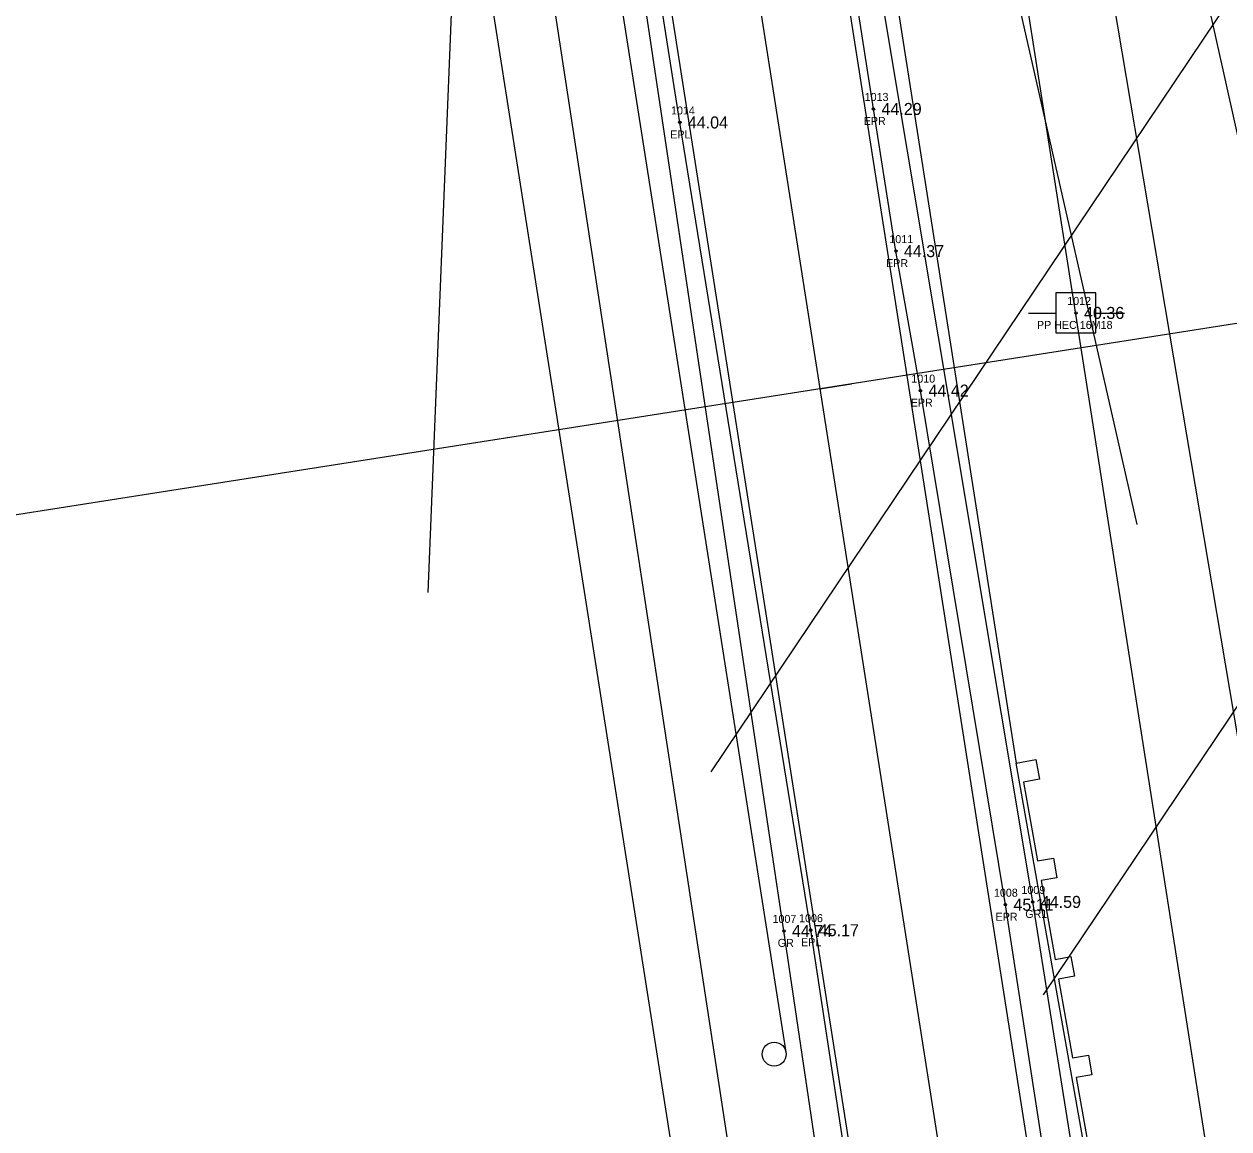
# Model space of a CAD drawing. Extents: x 2619568 to 2620316, y 784340 to 785138.
# Drawn here: x 2619755.9 to 2619906.4, y 784608.4 to 784746.5 of the extents above; entities that cross this region are included whole.
import ezdxf

# ---------------------------------------------------------------- set-up
doc = ezdxf.new("R2010")
doc.units = 0
for name, color, linetype in [('RD_EX_GuardRail', 7, 'Continuous'), ('RD_EX_GuardRail_txCode', 7, 'Continuous'), ('RD_EX_H2O', 7, 'Continuous'), ('RD_EX_Road', 7, 'Continuous'), ('RD_EX_Road_txCode', 7, 'Continuous'), ('RD_EX_RW', 7, 'Continuous'), ('RD_EX_TX_GuardRail_ELEV', 7, 'Continuous'), ('RD_EX_TX_Road_ELEV', 7, 'Continuous'), ('RD_EX_UT', 7, 'Continuous'), ('RD_EX_UT_txCode', 7, 'Continuous'), ('RD_EX_VEG', 7, 'Continuous'), ('RD_HC_Cl', 7, 'Continuous'), ('RD_HC_Data_Tic', 7, 'Continuous'), ('RD_HC_Survey_ELEV', 7, 'Continuous'), ('RD_PD_Final_TrvlWay', 7, 'Continuous'), ('RD_PD_GR', 7, 'Continuous'), ('RD_PD_PatLn1', 7, 'Continuous'), ('RD_PD_PatLn2', 7, 'Continuous'), ('RD_SMD_Locator', 7, 'Continuous')]:
    doc.layers.add(name, color=color, linetype=linetype)

msp = doc.modelspace()

# ---------------------------------------------------------------- linework, layer by layer
at = {"layer": 'RD_EX_GuardRail'}
for points in [[(2619867.12, 784523.3), (2619850.86, 784633.15), (2619824.72, 784807.66), (2619818.35, 784847.92), (2619803.75, 784935.38), (2619787.81, 785031.17), (2619775.16, 785106.97)], [(2619898.96, 784529.78), (2619881.94, 784636.77), (2619850.55, 784824.95), (2619844.25, 784865.7), (2619839.24, 784902.52)]]:
    msp.add_lwpolyline(points, dxfattribs=at)
at = {"layer": 'RD_EX_H2O'}
msp.add_lwpolyline([(2619858.79, 784802.44), (2619861.97, 784802.62), (2619885.46, 784800.96), (2619898.93, 784793.37), (2619901.36, 784760.21), (2619910.66, 784718.33), (2619929.66, 784699.53), (2619944.47, 784658), (2619963.48, 784625.35)], dxfattribs=at)
at = {"layer": 'RD_EX_Road'}
for p, q in [((2619837.85, 784734.18), (2619826.43, 784806.91)), ((2619862.04, 784735.87), (2619857.49, 784765.12)), ((2619864.84, 784718.1), (2619862.04, 784735.87)), ((2619854.2, 784633.24), (2619837.85, 784734.18)), ((2619867.91, 784700.67), (2619864.84, 784718.1)), ((2619878.52, 784636.42), (2619867.91, 784700.67)), ((2619895.76, 784524.85), (2619878.52, 784636.42)), ((2619871.29, 784521.47), (2619854.2, 784633.24))]:
    msp.add_line(p, q, dxfattribs=at)
at = {"layer": 'RD_EX_RW'}
for p, q in [((2619822.1, 785125.87), (2619915.04, 784533.11)), ((2619756.9, 785115.64), (2619849.84, 784522.89))]:
    msp.add_line(p, q, dxfattribs=at)
at = {"layer": 'RD_EX_UT'}
for p, q in [((2619889.83, 784712.89), (2619884.83, 784712.89)), ((2619884.83, 784712.89), (2619884.83, 784707.89)), ((2619889.83, 784707.89), (2619889.83, 784712.89)), ((2619881.4, 784710.33), (2619884.87, 784710.33)), ((2619889.76, 784710.33), (2619893.4, 784710.33)), ((2619884.83, 784707.89), (2619889.83, 784707.89))]:
    msp.add_line(p, q, dxfattribs=at)
at = {"layer": 'RD_EX_VEG'}
for points in [[(2619930.82, 784519.47), (2619827.3, 785132.88)], [(2619857.01, 784520.73), (2619804.77, 784862.84), (2619772.02, 785124.21)]]:
    msp.add_lwpolyline(points, dxfattribs=at)
at = {"layer": 'RD_HC_Cl'}
msp.add_line((2619789.5, 785120.76), (2619882.44, 784528), dxfattribs=at)
at = {"layer": 'RD_HC_Data_Tic'}
msp.add_line((2619855.33, 784700.88), (2619859.28, 784701.5), dxfattribs=at)
at = {"layer": 'RD_PD_Final_TrvlWay'}
for p, q in [((2619804.24, 785097.76), (2619881.69, 784603.8)), ((2619782.51, 785094.35), (2619859.95, 784600.39))]:
    msp.add_line(p, q, dxfattribs=at)
at = {"layer": 'RD_PD_GR'}
for p, q in [((2619851.12, 784617.98), (2619784.32, 785044.03)), ((2619845.02, 784876.41), (2619879.87, 784654.12))]:
    msp.add_line(p, q, dxfattribs=at)
msp.add_lwpolyline([(2619888.6, 784604.89), (2619879.87, 784654.12), (2619882.33, 784654.56), (2619882.77, 784652.1), (2619880.79, 784651.75), (2619882.54, 784641.9), (2619884.52, 784642.25), (2619884.95, 784639.79), (2619882.98, 784639.44), (2619884.72, 784629.59), (2619886.7, 784629.94), (2619887.14, 784627.48), (2619885.16, 784627.13), (2619886.9, 784617.28), (2619888.88, 784617.63), (2619889.32, 784615.17), (2619887.34, 784614.82), (2619889.09, 784604.98), (2619890.37, 784603.44), (2619887.92, 784603.01)], close=True, dxfattribs=at)
msp.add_circle((2619849.64, 784617.75), 1.5, dxfattribs=at)
at = {"layer": 'RD_PD_PatLn1'}
msp.add_line((2620003.52, 784724.12), (2619707.14, 784677.65), dxfattribs=at)
at = {"layer": 'RD_PD_PatLn2'}
for p, q in [((2619828.58, 784976.51), (2619894.93, 784683.94)), ((2619818.47, 784975.2), (2619806.39, 784675.45)), ((2620008.98, 784902.09), (2619841.72, 784653.04)), ((2620050.49, 784874.21), (2619883.23, 784625.16))]:
    msp.add_line(p, q, dxfattribs=at)
at = {"layer": 'RD_SMD_Locator'}
for centre in [(2619862.04, 784735.87), (2619837.85, 784734.18), (2619864.84, 784718.1), (2619887.34, 784710.38), (2619867.91, 784700.67), (2619878.52, 784636.42), (2619881.94, 784636.77), (2619850.86, 784633.15), (2619854.2, 784633.24)]:
    msp.add_circle(centre, 0.15, dxfattribs=at)

# ---------------------------------------------------------------- texts
at = {"layer": 'RD_EX_GuardRail_txCode'}
for s, p in [('1009', (2619880.52, 784637.77)), ('1007', (2619849.43, 784634.15)), ('GR1', (2619881, 784634.77)), ('GR', (2619850.08, 784631.15))]:
    msp.add_text(s, height=1, dxfattribs=at).set_placement(p)
at = {"layer": 'RD_EX_Road_txCode'}
for s, p in [('1013', (2619860.94, 784736.87)), ('1014', (2619836.75, 784735.18)), ('EPR', (2619860.82, 784733.87)), ('EPL', (2619836.65, 784732.18)), ('1011', (2619864.02, 784719.1)), ('EPR', (2619863.61, 784716.1)), ('1010', (2619866.77, 784701.67)), ('EPR', (2619866.69, 784698.67)), ('1008', (2619877.09, 784637.42)), ('1006', (2619852.75, 784634.24)), ('EPR', (2619877.29, 784634.42)), ('EPL', (2619852.99, 784631.24))]:
    msp.add_text(s, height=1, dxfattribs=at).set_placement(p)
at = {"layer": 'RD_EX_TX_GuardRail_ELEV'}
for s, p in [('44.59', (2619882.94, 784636.02)), ('44.74', (2619851.86, 784632.4))]:
    msp.add_text(s, height=1.5, dxfattribs=at).set_placement(p)
at = {"layer": 'RD_EX_TX_Road_ELEV'}
for s, p in [('44.29', (2619863.04, 784735.12)), ('44.04', (2619838.85, 784733.43)), ('44.37', (2619865.84, 784717.35)), ('44.42', (2619868.91, 784699.92)), ('45.11', (2619879.52, 784635.67)), ('45.17', (2619855.2, 784632.49))]:
    msp.add_text(s, height=1.5, dxfattribs=at).set_placement(p)
at = {"layer": 'RD_EX_UT_txCode'}
for s, p in [('1012', (2619886.24, 784711.38)), ('PP HEC 16M18', (2619882.46, 784708.38))]:
    msp.add_text(s, height=1, dxfattribs=at).set_placement(p)
at = {"layer": 'RD_HC_Survey_ELEV'}
msp.add_text('40.36', height=1.5, dxfattribs=at).set_placement((2619888.34, 784709.63))

doc.saveas('drawing.dxf')
